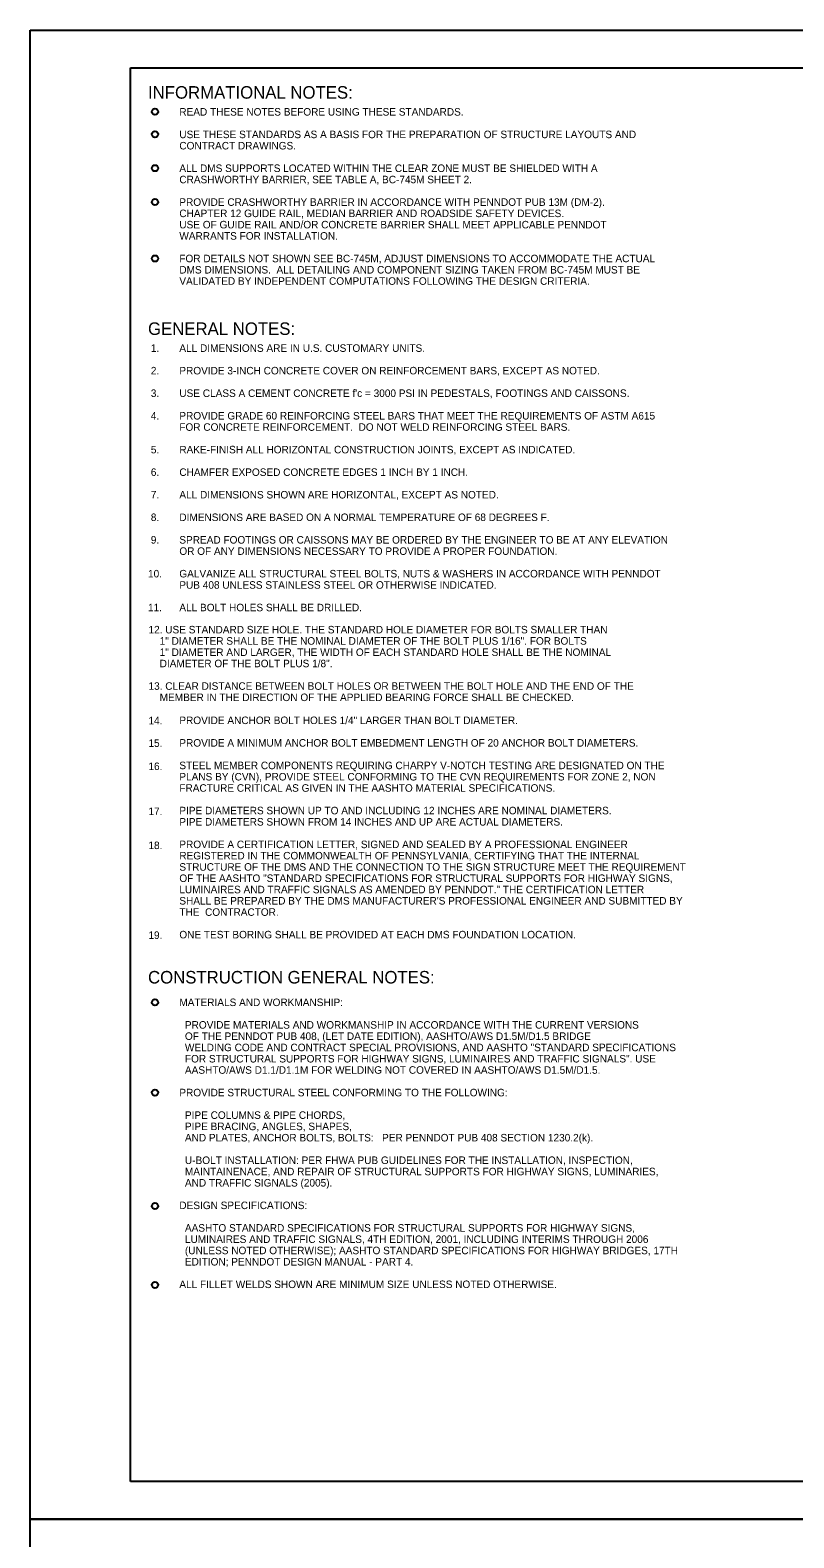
# Model space of a CAD drawing. Extents: x 3831399 to 3833095, y 499014 to 500202.
# Drawn here: x 3831399 to 3831704, y 499601 to 500202 of the extents above; entities that cross this region are included whole.
import ezdxf

# ---------------------------------------------------------------- set-up
doc = ezdxf.new("R2010")
doc.units = 0
for name, color, linetype in [('10', 7, 'Continuous'), ('2', 7, 'Continuous'), ('DIM TXT', 7, 'Continuous'), ('PLT-BNDY', 7, 'Continuous')]:
    doc.layers.add(name, color=color, linetype=linetype)

msp = doc.modelspace()

# ---------------------------------------------------------------- linework, layer by layer
at = {"layer": '2'}
for p, q in [((3831439.16, 499623.03), (3831439.16, 500187.03)), ((3831439.16, 500187.03), (3832225.16, 500187.03)), ((3832225.16, 499623.03), (3831439.16, 499623.03))]:
    msp.add_line(p, q, dxfattribs=at)
at = {"layer": 'DIM TXT'}
for centre in [(3831449, 500169.47), (3831449, 500160.47), (3831449, 500146.98), (3831449, 500133.44), (3831449, 500110.94), (3831448.99, 499814.15), (3831448.99, 499778.15), (3831448.99, 499732.91), (3831448.99, 499701.41)]:
    msp.add_circle(centre, 1.25, dxfattribs=at)
at = {"layer": 'PLT-BNDY'}
for points in [[(3831399.16, 500202.03), (3832240.16, 500202.03), (3832240.16, 499608.03), (3831399.16, 499608.03)], [(3831399.16, 499608.03), (3832240.16, 499608.03), (3832240.16, 499014.03), (3831399.16, 499014.03)]]:
    msp.add_lwpolyline(points, close=True, dxfattribs=at)

# ---------------------------------------------------------------- texts
at = {"layer": '10'}
for s, p in [('12. USE STANDARD SIZE HOLE. THE STANDARD HOLE DIAMETER FOR BOLTS SMALLER THAN', (3831446.41, 499961.36)), ('    1" DIAMETER SHALL BE THE NOMINAL DIAMETER OF THE BOLT PLUS 1/16". FOR BOLTS', (3831446.41, 499956.86)), ('    1" DIAMETER AND LARGER, THE WIDTH OF EACH STANDARD HOLE SHALL BE THE NOMINAL', (3831446.41, 499952.36)), ('    DIAMETER OF THE BOLT PLUS 1/8".', (3831446.41, 499947.86)), ('13. CLEAR DISTANCE BETWEEN BOLT HOLES OR BETWEEN THE BOLT HOLE AND THE END OF THE', (3831446.41, 499938.86)), ('    MEMBER IN THE DIRECTION OF THE APPLIED BEARING FORCE SHALL BE CHECKED.', (3831446.41, 499934.36))]:
    msp.add_text(s, height=3, dxfattribs=at).set_placement(p)
at = {"layer": 'DIM TXT'}
for s, height, p in [('INFORMATIONAL NOTES:', 4.9999, (3831446.22, 500174.69)), ('READ THESE NOTES BEFORE USING THESE STANDARDS. ', 2.9999, (3831458.72, 500167.94)), ('USE THESE STANDARDS AS A BASIS FOR THE PREPARATION OF STRUCTURE LAYOUTS AND ', 2.9999, (3831458.72, 500158.94)), ('CONTRACT DRAWINGS. ', 2.9999, (3831458.72, 500154.44)), ('ALL DMS SUPPORTS LOCATED WITHIN THE CLEAR ZONE MUST BE SHIELDED WITH A ', 2.9999, (3831458.72, 500145.44)), ('CRASHWORTHY BARRIER, SEE TABLE A, BC-745M SHEET 2.', 2.9999, (3831458.72, 500140.94)), ('CHAPTER 12 GUIDE RAIL, MEDIAN BARRIER AND ROADSIDE SAFETY DEVICES. ', 2.9999, (3831458.72, 500127.44)), ('PROVIDE CRASHWORTHY BARRIER IN ACCORDANCE WITH PENNDOT PUB 13M (DM-2).', 2.9999, (3831458.72, 500131.94)), ('USE OF GUIDE RAIL AND/OR CONCRETE BARRIER SHALL MEET APPLICABLE PENNDOT', 2.9999, (3831458.72, 500122.94)), ('WARRANTS FOR INSTALLATION.', 2.9999, (3831458.72, 500118.44)), ('FOR DETAILS NOT SHOWN SEE BC-745M, ADJUST DIMENSIONS TO ACCOMMODATE THE ACTUAL ', 2.9999, (3831458.72, 500109.44)), ('DMS DIMENSIONS.  ALL DETAILING AND COMPONENT SIZING TAKEN FROM BC-745M MUST BE ', 2.9999, (3831458.72, 500104.94)), ('VALIDATED BY INDEPENDENT COMPUTATIONS FOLLOWING THE DESIGN CRITERIA.', 2.9999, (3831458.72, 500100.44)), ('GENERAL NOTES:', 4.9999, (3831446.22, 500080.44)), (' 1.', 3, (3831446.22, 500073.69)), ('ALL DIMENSIONS ARE IN U.S. CUSTOMARY UNITS.', 2.9999, (3831458.72, 500073.69)), (' 2.', 3, (3831446.22, 500064.69)), ('PROVIDE 3-INCH CONCRETE COVER ON REINFORCEMENT BARS, EXCEPT AS NOTED.', 2.9999, (3831458.72, 500064.69)), (' 3.', 3, (3831446.22, 500055.69)), ("USE CLASS A CEMENT CONCRETE f'c = 3000 PSI IN PEDESTALS, FOOTINGS AND CAISSONS.", 2.9999, (3831458.72, 500055.69)), (' 4.', 3, (3831446.22, 500046.69)), ('PROVIDE GRADE 60 REINFORCING STEEL BARS THAT MEET THE REQUIREMENTS OF ASTM A615 ', 2.9999, (3831458.72, 500046.69)), ('FOR CONCRETE REINFORCEMENT.  DO NOT WELD REINFORCING STEEL BARS.', 2.9999, (3831458.72, 500042.19)), (' 5.', 3, (3831446.22, 500033.19)), ('RAKE-FINISH ALL HORIZONTAL CONSTRUCTION JOINTS, EXCEPT AS INDICATED.', 2.9999, (3831458.72, 500033.19)), (' 6.', 3, (3831446.22, 500024.19)), ('CHAMFER EXPOSED CONCRETE EDGES 1 INCH BY 1 INCH.', 2.9999, (3831458.72, 500024.19)), (' 7.', 3, (3831446.22, 500015.19)), ('ALL DIMENSIONS SHOWN ARE HORIZONTAL, EXCEPT AS NOTED.', 2.9999, (3831458.72, 500015.19)), (' 8.', 3, (3831446.22, 500006.19)), ('DIMENSIONS ARE BASED ON A NORMAL TEMPERATURE OF 68 DEGREES F.', 2.9999, (3831458.72, 500006.19)), (' 9.', 3, (3831446.22, 499997.19)), ('SPREAD FOOTINGS OR CAISSONS MAY BE ORDERED BY THE ENGINEER TO BE AT ANY ELEVATION ', 2.9999, (3831458.72, 499997.19)), ('OR OF ANY DIMENSIONS NECESSARY TO PROVIDE A PROPER FOUNDATION.', 2.9999, (3831458.72, 499992.69)), ('10.', 3, (3831446.22, 499983.69)), ('GALVANIZE ALL STRUCTURAL STEEL BOLTS, NUTS & WASHERS IN ACCORDANCE WITH PENNDOT ', 2.9999, (3831458.72, 499983.69)), ('PUB 408 UNLESS STAINLESS STEEL OR OTHERWISE INDICATED.', 2.9999, (3831458.72, 499979.19)), ('11.', 3, (3831446.22, 499970.19)), ('ALL BOLT HOLES SHALL BE DRILLED.', 2.9999, (3831458.72, 499970.19)), ('14.', 3, (3831446.38, 499925.09)), ('PROVIDE ANCHOR BOLT HOLES 1/4" LARGER THAN BOLT DIAMETER.', 2.9999, (3831458.72, 499925.19)), ('15.', 3, (3831446.38, 499916.09)), ('PROVIDE A MINIMUM ANCHOR BOLT EMBEDMENT LENGTH OF 20 ANCHOR BOLT DIAMETERS.', 2.9999, (3831458.72, 499916.19)), ('16.', 3, (3831446.38, 499906.85)), ('STEEL MEMBER COMPONENTS REQUIRING CHARPY V-NOTCH TESTING ARE DESIGNATED ON THE ', 2.9999, (3831458.72, 499907.19)), ('PLANS BY (CVN), PROVIDE STEEL CONFORMING TO THE CVN REQUIREMENTS FOR ZONE 2, NON ', 2.9999, (3831458.72, 499902.69)), ('FRACTURE CRITICAL AS GIVEN IN THE AASHTO MATERIAL SPECIFICATIONS.', 2.9999, (3831458.72, 499898.19)), ('17.', 3, (3831446.38, 499888.88)), ('PIPE DIAMETERS SHOWN UP TO AND INCLUDING 12 INCHES ARE NOMINAL DIAMETERS.', 2.9999, (3831458.72, 499889.19)), ('PIPE DIAMETERS SHOWN FROM 14 INCHES AND UP ARE ACTUAL DIAMETERS.', 2.9999, (3831458.72, 499884.69)), ('18.', 3, (3831446.38, 499875.31)), ('PROVIDE A CERTIFICATION LETTER, SIGNED AND SEALED BY A PROFESSIONAL ENGINEER ', 2.9999, (3831458.72, 499875.69)), ('REGISTERED IN THE COMMONWEALTH OF PENNSYLVANIA, CERTIFYING THAT THE INTERNAL ', 2.9999, (3831458.72, 499871.19)), ('STRUCTURE OF THE DMS AND THE CONNECTION TO THE SIGN STRUCTURE MEET THE REQUIREMENT ', 2.9999, (3831458.72, 499866.69)), ('OF THE AASHTO "STANDARD SPECIFICATIONS FOR STRUCTURAL SUPPORTS FOR HIGHWAY SIGNS,', 2.9999, (3831458.72, 499862.19)), ('LUMINAIRES AND TRAFFIC SIGNALS AS AMENDED BY PENNDOT." THE CERTIFICATION LETTER ', 2.9999, (3831458.72, 499857.69)), ("SHALL BE PREPARED BY THE DMS MANUFACTURER'S PROFESSIONAL ENGINEER AND SUBMITTED BY ", 2.9999, (3831458.72, 499853.19)), ('THE  CONTRACTOR.', 2.9999, (3831458.72, 499848.69)), ('19.', 3, (3831446.38, 499839.46)), ('ONE TEST BORING SHALL BE PROVIDED AT EACH DMS FOUNDATION LOCATION.', 2.9999, (3831458.72, 499839.69)), ('CONSTRUCTION GENERAL NOTES:', 4.9999, (3831446.22, 499821.69)), ('MATERIALS AND WORKMANSHIP:', 2.9999, (3831458.72, 499812.68)), ('  PROVIDE MATERIALS AND WORKMANSHIP IN ACCORDANCE WITH THE CURRENT VERSIONS ', 2.9999, (3831458.72, 499803.68)), ('  OF THE PENNDOT PUB 408, (LET DATE EDITION), AASHTO/AWS D1.5M/D1.5 BRIDGE', 2.9999, (3831458.72, 499799.18)), ('  WELDING CODE AND CONTRACT SPECIAL PROVISIONS, AND AASHTO "STANDARD SPECIFICATIONS', 2.9999, (3831458.72, 499794.68)), ('  FOR STRUCTURAL SUPPORTS FOR HIGHWAY SIGNS, LUMINAIRES AND TRAFFIC SIGNALS". USE', 2.9999, (3831458.72, 499790.18)), ('  AASHTO/AWS D1.1/D1.1M FOR WELDING NOT COVERED IN AASHTO/AWS D1.5M/D1.5.', 2.9999, (3831458.72, 499785.68)), ('PROVIDE STRUCTURAL STEEL CONFORMING TO THE FOLLOWING:', 2.9999, (3831458.72, 499776.68)), ('  PIPE COLUMNS & PIPE CHORDS,', 2.9999, (3831458.72, 499767.68)), ('  PIPE BRACING, ANGLES, SHAPES,', 2.9999, (3831458.72, 499763.18)), ('  AND PLATES, ANCHOR BOLTS, BOLTS:   PER PENNDOT PUB 408 SECTION 1230.2(k).', 2.9999, (3831458.72, 499758.68)), ('  U-BOLT INSTALLATION: PER FHWA PUB GUIDELINES FOR THE INSTALLATION, INSPECTION,', 2.9999, (3831458.72, 499749.68)), ('  MAINTAINENACE, AND REPAIR OF STRUCTURAL SUPPORTS FOR HIGHWAY SIGNS, LUMINARIES,', 2.9999, (3831458.72, 499745.18)), ('  AND TRAFFIC SIGNALS (2005).', 2.9999, (3831458.72, 499740.68)), ('DESIGN SPECIFICATIONS:', 2.9999, (3831458.72, 499731.68)), ('  AASHTO STANDARD SPECIFICATIONS FOR STRUCTURAL SUPPORTS FOR HIGHWAY SIGNS,', 2.9999, (3831458.72, 499722.68)), ('  LUMINAIRES AND TRAFFIC SIGNALS, 4TH EDITION, 2001, INCLUDING INTERIMS THROUGH 2006', 2.9999, (3831458.72, 499718.18)), ('  (UNLESS NOTED OTHERWISE); AASHTO STANDARD SPECIFICATIONS FOR HIGHWAY BRIDGES, 17TH', 2.9999, (3831458.72, 499713.68)), ('  EDITION; PENNDOT DESIGN MANUAL - PART 4.', 2.9999, (3831458.72, 499709.18)), ('ALL FILLET WELDS SHOWN ARE MINIMUM SIZE UNLESS NOTED OTHERWISE.', 2.9999, (3831458.72, 499700.18))]:
    msp.add_text(s, height=height, dxfattribs=at).set_placement(p)

doc.saveas('drawing.dxf')
